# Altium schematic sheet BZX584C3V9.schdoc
size 127 x 101 mm
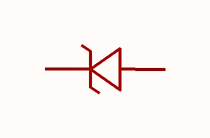
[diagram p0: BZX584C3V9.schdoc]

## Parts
D?  bzx584c3v9  [SOD-523_L1.2-W0.8-LS1.6-RD]  (value not drawn)

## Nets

Not connected (* = marked no-connect by the designer): D? 1(A) 2(K)

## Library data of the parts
D? = bzx584c3v9: 二极管配置:1个独立式;稳压值(标称值):3.9V;稳压值(范围值):3.7V~4.1V;耗散功率(Pd):150mW;; Manufacturer: CJ(江苏长电/长晶); AddInBom: yes; ModelId: 8f56a03db567494d8f4c9d12aa52a741; ModelName: SOD-523_L1.2-W0.8-H0.7-LS1.6; ModelTransform: 62.992,31.496,0,180,0,0,0,0,0; Diode Configuration: 1个独立式; Zener Voltage(Nom): 3.9V; Reverse Leakage Current (Ir): 3uA@1V; Pd - Power Dissipation: 150mW; Impedance(Zzt): 90Ω; Impedance(Zzk): 600Ω; Operating Junction Temperature Range: -55℃~+150℃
